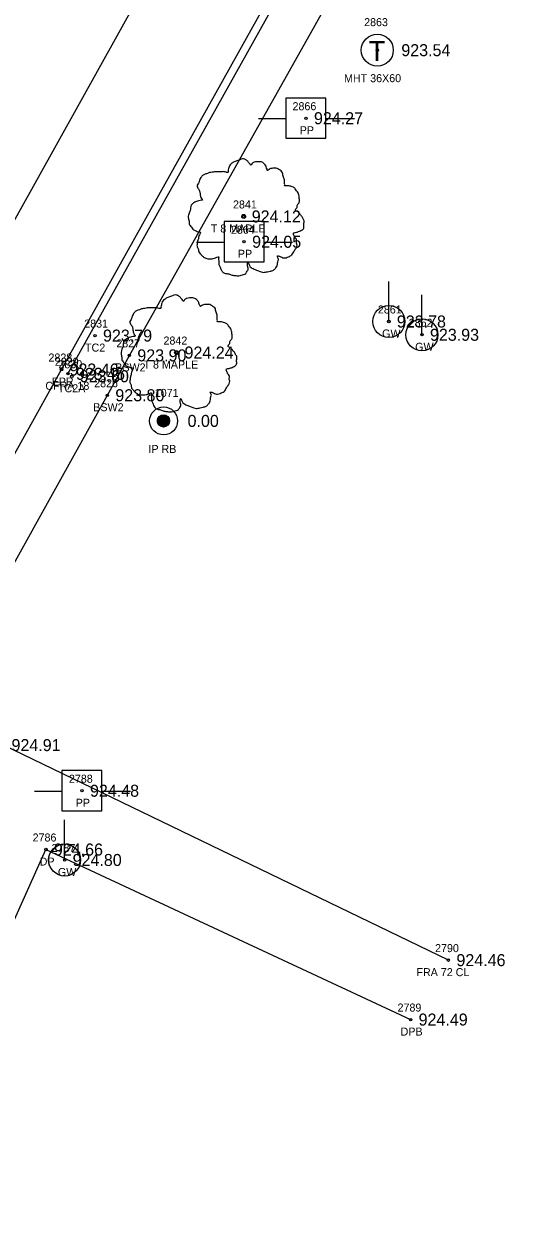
# Model space of a CAD drawing. Extents: x 1575382 to 1578175, y 1099175 to 1101955.
# Drawn here: x 1577042 to 1577102.8, y 1100555.1 to 1100704 of the extents above; entities that cross this region are included whole.
import ezdxf

# ---------------------------------------------------------------- set-up
doc = ezdxf.new("R2010")
doc.units = 0
for name, color, linetype in [('RD_EX_Conc', 7, 'Continuous'), ('RD_EX_Conc_txCode', 7, 'Continuous'), ('RD_EX_Driveway', 7, 'Continuous'), ('RD_EX_Driveway_txCode', 7, 'Continuous'), ('RD_EX_DV_Prop_txCode', 7, 'Continuous'), ('RD_EX_DV_PropPin', 7, 'Continuous'), ('RD_EX_Fence_Other', 7, 'Continuous'), ('RD_EX_Fence_Other_txCode', 7, 'Continuous'), ('RD_EX_Road', 7, 'Continuous'), ('RD_EX_Road_txCode', 7, 'Continuous'), ('RD_EX_SU_Telecom', 7, 'Continuous'), ('RD_EX_TX_Conc_ELEV', 7, 'Continuous'), ('RD_EX_TX_Driveway_ELEV', 7, 'Continuous'), ('RD_EX_TX_DV_Prop_ELEV', 7, 'Continuous'), ('RD_EX_TX_Fence_Other_ELEV', 7, 'Continuous'), ('RD_EX_TX_Road_ELEV', 7, 'Continuous'), ('RD_EX_TX_UT_ELEV', 7, 'Continuous'), ('RD_EX_TX_VEG_ELEV', 7, 'Continuous'), ('RD_EX_UT', 7, 'Continuous'), ('RD_EX_UT_txCode', 7, 'Continuous'), ('RD_EX_VEG', 7, 'Continuous'), ('RD_EX_VEG_txCode', 7, 'Continuous'), ('RD_HC_Cl', 7, 'Continuous'), ('RD_HC_Survey_ELEV', 7, 'Continuous'), ('RD_SMD_Locator', 7, 'Continuous')]:
    doc.layers.add(name, color=color, linetype=linetype)

msp = doc.modelspace()

# ---------------------------------------------------------------- linework, layer by layer
at = {"layer": 'RD_EX_Conc'}
for points in [[(1577047.47, 1100660.34), (1577079.61, 1100717.86), (1577079.61, 1100717.86), (1577102.32, 1100758.52), (1577114.19, 1100779.63), (1577126.08, 1100804.34)], [(1576925.28, 1100434.6), (1576931.32, 1100441.65), (1576943.72, 1100456.06), (1576959.8, 1100485.15), (1576962.79, 1100490.55), (1576976.91, 1100516.3), (1576979.99, 1100521.81), (1576994.08, 1100547.41), (1577013.9, 1100582.65), (1577028.01, 1100607.52), (1577031.93, 1100618.57), (1577033.8, 1100624.22), (1577052.4, 1100657.66), (1577055.15, 1100662.64), (1577085.17, 1100716.01)]]:
    msp.add_lwpolyline(points, dxfattribs=at)
at = {"layer": 'RD_EX_Driveway'}
msp.add_lwpolyline([(1577065.95, 1100460.35), (1577042.55, 1100463.11), (1577001.85, 1100499.13), (1577008.49, 1100516.59), (1577022.64, 1100551.7), (1577044.72, 1100600.92), (1577090.31, 1100579.68)], dxfattribs=at)
at = {"layer": 'RD_EX_DV_PropPin'}
for p, q in [((1577058.69, 1100654.26), (1577058.69, 1100654.65)), ((1577058.73, 1100654.16), (1577058.73, 1100654.75)), ((1577058.76, 1100654.08), (1577058.76, 1100654.82)), ((1577058.8, 1100654.03), (1577058.8, 1100654.88)), ((1577058.83, 1100653.98), (1577058.83, 1100654.93)), ((1577058.87, 1100653.94), (1577058.87, 1100654.97)), ((1577058.9, 1100653.9), (1577058.9, 1100655)), ((1577058.94, 1100653.87), (1577058.94, 1100655.04)), ((1577058.97, 1100653.84), (1577058.97, 1100655.06)), ((1577059.01, 1100653.82), (1577059.01, 1100655.09)), ((1577059.04, 1100653.8), (1577059.04, 1100655.11)), ((1577059.08, 1100653.78), (1577059.08, 1100655.13)), ((1577059.11, 1100653.76), (1577059.11, 1100655.15)), ((1577059.15, 1100653.75), (1577059.15, 1100655.16)), ((1577059.18, 1100653.73), (1577059.18, 1100655.17)), ((1577059.22, 1100653.72), (1577059.22, 1100655.18)), ((1577059.25, 1100653.71), (1577059.25, 1100655.19)), ((1577059.29, 1100653.7), (1577059.29, 1100655.2)), ((1577059.32, 1100653.7), (1577059.32, 1100655.21)), ((1577059.36, 1100653.7), (1577059.36, 1100655.21)), ((1577059.39, 1100653.69), (1577059.39, 1100655.21)), ((1577059.43, 1100653.69), (1577059.43, 1100655.21)), ((1577059.46, 1100653.69), (1577059.46, 1100655.21)), ((1577059.5, 1100653.7), (1577059.5, 1100655.21)), ((1577059.53, 1100653.7), (1577059.53, 1100655.21)), ((1577059.57, 1100653.7), (1577059.57, 1100655.2)), ((1577059.6, 1100653.71), (1577059.6, 1100655.19)), ((1577059.64, 1100653.72), (1577059.64, 1100655.18)), ((1577059.67, 1100653.73), (1577059.67, 1100655.17)), ((1577059.71, 1100653.75), (1577059.71, 1100655.16)), ((1577059.74, 1100653.76), (1577059.74, 1100655.15)), ((1577059.78, 1100653.78), (1577059.78, 1100655.13)), ((1577059.81, 1100653.8), (1577059.81, 1100655.11)), ((1577059.85, 1100653.82), (1577059.85, 1100655.09)), ((1577059.88, 1100653.84), (1577059.88, 1100655.06)), ((1577059.92, 1100653.87), (1577059.92, 1100655.04)), ((1577059.95, 1100653.9), (1577059.95, 1100655)), ((1577059.99, 1100653.94), (1577059.99, 1100654.97)), ((1577060.02, 1100653.98), (1577060.02, 1100654.93)), ((1577060.06, 1100654.03), (1577060.06, 1100654.88)), ((1577060.09, 1100654.08), (1577060.09, 1100654.82)), ((1577060.13, 1100654.16), (1577060.13, 1100654.75)), ((1577060.16, 1100654.26), (1577060.16, 1100654.65))]:
    msp.add_line(p, q, dxfattribs=at)
for radius in [1.75, 0.761]:
    msp.add_circle((1577059.43, 1100654.45), radius, dxfattribs=at)
at = {"layer": 'RD_EX_Fence_Other'}
msp.add_lwpolyline([(1577095.04, 1100587.1), (1577039.42, 1100613.96), (1576993.42, 1100500.9)], dxfattribs=at)
at = {"layer": 'RD_EX_Road'}
msp.add_lwpolyline([(1576918.43, 1100436.45), (1576919.69, 1100438.1), (1576919.21, 1100438.45), (1576924.62, 1100446.41), (1576935.15, 1100461.4), (1576954.41, 1100495.42), (1576968.8, 1100521.52), (1576985.92, 1100552.3), (1577005.62, 1100587.42), (1577028.14, 1100627.58), (1577046.67, 1100660.87), (1577078.76, 1100718.33)], dxfattribs=at)
at = {"layer": 'RD_EX_SU_Telecom'}
msp.add_circle((1577086.15, 1100700.76), 2, dxfattribs=at)
at = {"layer": 'RD_EX_UT'}
for p, q in [((1577079.72, 1100694.77), (1577074.72, 1100694.77)), ((1577074.72, 1100694.77), (1577074.72, 1100689.77)), ((1577079.72, 1100689.77), (1577079.72, 1100694.77)), ((1577071.29, 1100692.21), (1577074.76, 1100692.21)), ((1577079.65, 1100692.21), (1577083.29, 1100692.21)), ((1577074.72, 1100689.77), (1577079.72, 1100689.77)), ((1577072, 1100679.34), (1577067, 1100679.34)), ((1577067, 1100679.34), (1577067, 1100674.34)), ((1577072, 1100674.34), (1577072, 1100679.34)), ((1577063.56, 1100676.78), (1577067.03, 1100676.78)), ((1577071.92, 1100676.78), (1577075.56, 1100676.78)), ((1577067, 1100674.34), (1577072, 1100674.34)), ((1577087.59, 1100666.87), (1577087.59, 1100671.87)), ((1577091.73, 1100665.21), (1577091.73, 1100670.21)), ((1577051.72, 1100610.77), (1577046.72, 1100610.77)), ((1577046.72, 1100610.77), (1577046.72, 1100605.77)), ((1577051.72, 1100605.77), (1577051.72, 1100610.77)), ((1577043.29, 1100608.21), (1577046.76, 1100608.21)), ((1577051.65, 1100608.21), (1577055.29, 1100608.21)), ((1577046.72, 1100605.77), (1577051.72, 1100605.77)), ((1577047.06, 1100599.61), (1577047.06, 1100604.61))]:
    msp.add_line(p, q, dxfattribs=at)
for centre in [(1577087.59, 1100666.87), (1577091.73, 1100665.21), (1577047.06, 1100599.61)]:
    msp.add_circle(centre, 2, dxfattribs=at)
at = {"layer": 'RD_EX_VEG'}
for centre, radius in [((1577069.45, 1100679.99), 0.25), ((1577069.44, 1100679.97), 0.0001), ((1577061.05, 1100662.99), 0.25), ((1577061.03, 1100662.97), 0.0001)]:
    msp.add_circle(centre, radius, dxfattribs=at)
for points in [[(1577069.59, 1100687.16), (1577069.29, 1100687.18), (1577068.96, 1100687.08), (1577068.71, 1100686.98), (1577068.49, 1100686.91), (1577068.26, 1100686.81), (1577067.96, 1100686.63), (1577067.74, 1100686.43), (1577067.61, 1100686.18), (1577067.56, 1100685.96), (1577067.51, 1100685.68), (1577067.51, 1100685.51), (1577067.39, 1100685.48), (1577067.24, 1100685.51), (1577066.99, 1100685.58), (1577066.74, 1100685.58), (1577066.49, 1100685.58), (1577066.14, 1100685.56), (1577065.79, 1100685.56), (1577065.51, 1100685.51), (1577065.19, 1100685.46), (1577064.81, 1100685.33), (1577064.46, 1100685.21), (1577064.16, 1100684.96), (1577063.91, 1100684.48), (1577063.79, 1100684.13), (1577063.64, 1100683.88), (1577063.79, 1100683.43), (1577063.96, 1100683.08), (1577063.99, 1100682.88), (1577064.06, 1100682.46), (1577064.16, 1100682.23), (1577064.29, 1100682.03), (1577064.21, 1100682.01), (1577063.84, 1100681.96), (1577063.54, 1100681.86), (1577063.11, 1100681.63), (1577062.89, 1100681.41), (1577062.79, 1100681.08), (1577062.76, 1100680.73), (1577062.66, 1100680.53), (1577062.59, 1100680.26), (1577062.56, 1100680.18), (1577062.51, 1100679.86), (1577062.61, 1100679.41), (1577062.64, 1100679.06), (1577062.76, 1100678.84), (1577062.91, 1100678.66), (1577063.09, 1100678.41), (1577063.49, 1100678.19), (1577063.81, 1100678.09), (1577064.01, 1100678.06), (1577063.84, 1100677.56), (1577063.79, 1100677.21), (1577063.66, 1100676.81), (1577063.66, 1100676.74), (1577063.61, 1100676.26), (1577063.76, 1100675.94), (1577063.84, 1100675.56), (1577064.01, 1100675.34), (1577064.29, 1100675.04), (1577064.61, 1100674.81), (1577065.11, 1100674.69), (1577065.51, 1100674.71), (1577066.09, 1100674.89), (1577066.34, 1100674.96), (1577066.31, 1100674.79), (1577066.34, 1100674.41), (1577066.34, 1100673.99), (1577066.49, 1100673.66), (1577066.59, 1100673.39), (1577066.74, 1100673.14), (1577067.06, 1100672.91), (1577067.46, 1100672.84), (1577067.89, 1100672.69), (1577068.34, 1100672.61), (1577068.84, 1100672.59), (1577069.44, 1100672.74), (1577069.71, 1100672.86), (1577069.81, 1100673.04), (1577070.01, 1100673.41), (1577069.96, 1100673.64), (1577069.99, 1100674.24), (1577070.09, 1100674.06), (1577070.26, 1100673.71), (1577070.76, 1100673.41), (1577071.16, 1100673.24), (1577071.64, 1100673.09), (1577071.94, 1100673.01), (1577072.41, 1100673.09), (1577072.79, 1100673.16), (1577073.16, 1100673.29), (1577073.46, 1100673.56), (1577073.63, 1100673.84), (1577073.68, 1100674.11), (1577073.76, 1100674.49), (1577073.81, 1100674.66)], [(1577073.81, 1100674.66), (1577073.73, 1100674.84), (1577073.68, 1100675.09), (1577073.76, 1100675.06), (1577073.93, 1100675.01), (1577074.21, 1100674.89), (1577074.43, 1100674.81), (1577074.76, 1100674.84), (1577075.03, 1100674.94), (1577075.48, 1100675.21), (1577075.76, 1100675.69), (1577076.03, 1100676.09), (1577076.11, 1100676.41), (1577076.06, 1100676.64), (1577076.03, 1100677.14), (1577075.83, 1100677.39), (1577075.78, 1100677.51), (1577075.68, 1100677.91), (1577075.76, 1100677.96), (1577076.03, 1100678.01), (1577076.41, 1100678.14), (1577076.68, 1100678.26), (1577076.91, 1100678.44), (1577076.98, 1100678.66), (1577076.96, 1100679.06), (1577077.01, 1100679.46), (1577076.93, 1100679.61), (1577076.83, 1100679.76), (1577076.76, 1100679.96), (1577076.61, 1100680.11), (1577076.51, 1100680.26), (1577076.41, 1100680.36), (1577076.28, 1100680.51), (1577076.11, 1100680.63), (1577075.96, 1100680.68), (1577075.91, 1100680.83), (1577076.06, 1100681.03), (1577076.11, 1100681.13), (1577076.13, 1100681.36), (1577076.36, 1100681.71), (1577076.41, 1100682.11), (1577076.36, 1100682.53), (1577076.31, 1100682.81), (1577076.16, 1100683.08), (1577075.96, 1100683.33), (1577075.83, 1100683.51), (1577075.66, 1100683.63), (1577075.33, 1100683.76), (1577075.08, 1100683.81), (1577074.73, 1100683.81), (1577074.53, 1100683.86), (1577074.56, 1100683.91), (1577074.56, 1100684.06), (1577074.56, 1100684.33), (1577074.48, 1100684.78), (1577074.33, 1100685.28), (1577074.33, 1100685.31), (1577074.23, 1100685.56), (1577074.01, 1100685.76), (1577073.83, 1100685.86), (1577073.63, 1100685.98), (1577073.38, 1100686.01), (1577073.09, 1100686.01), (1577072.81, 1100685.96), (1577072.61, 1100685.86), (1577072.44, 1100685.73), (1577072.36, 1100685.88), (1577072.26, 1100686.18), (1577072.21, 1100686.33), (1577072.06, 1100686.51), (1577071.84, 1100686.71), (1577071.39, 1100686.83), (1577070.76, 1100686.76), (1577070.46, 1100686.56), (1577070.31, 1100686.38), (1577070.26, 1100686.51), (1577070.06, 1100686.71), (1577069.96, 1100686.88), (1577069.79, 1100687.01), (1577069.64, 1100687.11), (1577069.54, 1100687.16)], [(1577061.18, 1100670.16), (1577060.88, 1100670.18), (1577060.55, 1100670.08), (1577060.3, 1100669.98), (1577060.08, 1100669.91), (1577059.85, 1100669.81), (1577059.55, 1100669.63), (1577059.33, 1100669.43), (1577059.2, 1100669.18), (1577059.15, 1100668.96), (1577059.1, 1100668.68), (1577059.1, 1100668.51), (1577058.98, 1100668.48), (1577058.83, 1100668.51), (1577058.58, 1100668.58), (1577058.33, 1100668.58), (1577058.08, 1100668.58), (1577057.73, 1100668.56), (1577057.38, 1100668.56), (1577057.1, 1100668.51), (1577056.78, 1100668.46), (1577056.4, 1100668.33), (1577056.06, 1100668.21), (1577055.76, 1100667.96), (1577055.51, 1100667.49), (1577055.38, 1100667.14), (1577055.23, 1100666.89), (1577055.38, 1100666.44), (1577055.56, 1100666.09), (1577055.58, 1100665.89), (1577055.66, 1100665.46), (1577055.76, 1100665.24), (1577055.88, 1100665.04), (1577055.81, 1100665.01), (1577055.43, 1100664.96), (1577055.13, 1100664.86), (1577054.71, 1100664.64), (1577054.48, 1100664.41), (1577054.38, 1100664.09), (1577054.36, 1100663.74), (1577054.26, 1100663.54), (1577054.18, 1100663.26), (1577054.16, 1100663.19), (1577054.11, 1100662.86), (1577054.21, 1100662.41), (1577054.23, 1100662.06), (1577054.36, 1100661.84), (1577054.51, 1100661.66), (1577054.68, 1100661.41), (1577055.08, 1100661.19), (1577055.41, 1100661.09), (1577055.61, 1100661.06), (1577055.43, 1100660.56), (1577055.38, 1100660.21), (1577055.26, 1100659.81), (1577055.26, 1100659.74), (1577055.21, 1100659.26), (1577055.36, 1100658.94), (1577055.43, 1100658.56), (1577055.61, 1100658.34), (1577055.88, 1100658.04), (1577056.2, 1100657.81), (1577056.7, 1100657.69), (1577057.1, 1100657.71), (1577057.68, 1100657.89), (1577057.93, 1100657.96), (1577057.9, 1100657.79), (1577057.93, 1100657.41), (1577057.93, 1100656.99), (1577058.08, 1100656.67), (1577058.18, 1100656.39), (1577058.33, 1100656.14), (1577058.65, 1100655.92), (1577059.05, 1100655.84), (1577059.48, 1100655.69), (1577059.93, 1100655.62), (1577060.43, 1100655.59), (1577061.03, 1100655.74), (1577061.3, 1100655.87), (1577061.4, 1100656.04), (1577061.6, 1100656.42), (1577061.55, 1100656.64), (1577061.58, 1100657.24), (1577061.68, 1100657.06), (1577061.85, 1100656.71), (1577062.35, 1100656.42), (1577062.75, 1100656.24), (1577063.23, 1100656.09), (1577063.53, 1100656.02), (1577064, 1100656.09), (1577064.38, 1100656.17), (1577064.75, 1100656.29), (1577065.05, 1100656.57), (1577065.23, 1100656.84), (1577065.28, 1100657.11), (1577065.35, 1100657.49), (1577065.4, 1100657.66)], [(1577065.4, 1100657.66), (1577065.33, 1100657.84), (1577065.28, 1100658.09), (1577065.35, 1100658.06), (1577065.53, 1100658.01), (1577065.8, 1100657.89), (1577066.03, 1100657.81), (1577066.35, 1100657.84), (1577066.63, 1100657.94), (1577067.08, 1100658.21), (1577067.35, 1100658.69), (1577067.62, 1100659.09), (1577067.7, 1100659.41), (1577067.65, 1100659.64), (1577067.62, 1100660.14), (1577067.43, 1100660.39), (1577067.38, 1100660.51), (1577067.28, 1100660.91), (1577067.35, 1100660.96), (1577067.62, 1100661.01), (1577068, 1100661.14), (1577068.27, 1100661.26), (1577068.5, 1100661.44), (1577068.57, 1100661.66), (1577068.55, 1100662.06), (1577068.6, 1100662.46), (1577068.52, 1100662.61), (1577068.42, 1100662.76), (1577068.35, 1100662.96), (1577068.2, 1100663.11), (1577068.1, 1100663.26), (1577068, 1100663.36), (1577067.87, 1100663.51), (1577067.7, 1100663.64), (1577067.55, 1100663.69), (1577067.5, 1100663.84), (1577067.65, 1100664.04), (1577067.7, 1100664.14), (1577067.72, 1100664.36), (1577067.95, 1100664.71), (1577068, 1100665.11), (1577067.95, 1100665.54), (1577067.9, 1100665.81), (1577067.75, 1100666.09), (1577067.55, 1100666.34), (1577067.43, 1100666.51), (1577067.25, 1100666.64), (1577066.93, 1100666.76), (1577066.68, 1100666.81), (1577066.33, 1100666.81), (1577066.13, 1100666.86), (1577066.15, 1100666.91), (1577066.15, 1100667.06), (1577066.15, 1100667.34), (1577066.08, 1100667.79), (1577065.93, 1100668.28), (1577065.93, 1100668.31), (1577065.83, 1100668.56), (1577065.6, 1100668.76), (1577065.43, 1100668.86), (1577065.23, 1100668.98), (1577064.98, 1100669.01), (1577064.68, 1100669.01), (1577064.4, 1100668.96), (1577064.2, 1100668.86), (1577064.03, 1100668.73), (1577063.95, 1100668.88), (1577063.85, 1100669.18), (1577063.8, 1100669.33), (1577063.65, 1100669.51), (1577063.43, 1100669.71), (1577062.98, 1100669.83), (1577062.35, 1100669.76), (1577062.05, 1100669.56), (1577061.9, 1100669.38), (1577061.85, 1100669.51), (1577061.65, 1100669.71), (1577061.55, 1100669.88), (1577061.38, 1100670.01), (1577061.23, 1100670.11), (1577061.13, 1100670.16)]]:
    msp.add_spline(points, degree=3, dxfattribs=at)
at = {"layer": 'RD_HC_Cl'}
msp.add_line((1576888.29, 1100406.32), (1577092.18, 1100771.63), dxfattribs=at)
at = {"layer": 'RD_SMD_Locator'}
for centre in [(1577086.15, 1100700.76), (1577077.23, 1100692.26), (1577069.45, 1100679.99), (1577069.5, 1100676.83), (1577087.59, 1100666.87), (1577050.86, 1100665.11), (1577091.73, 1100665.21), (1577055.15, 1100662.64), (1577061.05, 1100662.99), (1577046.67, 1100660.87), (1577047.47, 1100660.34), (1577047.96, 1100660.03), (1577052.4, 1100657.66), (1577059.43, 1100654.45), (1577049.23, 1100608.26), (1577044.72, 1100600.92), (1577047.06, 1100599.61), (1577095.04, 1100587.1), (1577090.31, 1100579.68)]:
    msp.add_circle(centre, 0.15, dxfattribs=at)

# ---------------------------------------------------------------- texts
at = {"layer": 'RD_EX_Conc_txCode'}
for s, p in [('2831', (1577049.51, 1100666.11)), ('2827', (1577053.52, 1100663.64)), ('TC2', (1577049.61, 1100663.11)), ('2829', (1577045.84, 1100661.34)), ('2830', (1577046.29, 1100661.03)), ('BSW2', (1577053.39, 1100660.64)), ('CFRA 18', (1577044.65, 1100658.34)), ('TC2A', (1577046.23, 1100658.03)), ('2826', (1577050.75, 1100658.66)), ('BSW2', (1577050.64, 1100655.66))]:
    msp.add_text(s, height=1, dxfattribs=at).set_placement(p)
at = {"layer": 'RD_EX_Driveway_txCode'}
for s, p in [('2786', (1577043.06, 1100601.92)), ('DP', (1577043.94, 1100598.92)), ('2789', (1577088.68, 1100580.68)), ('DPB', (1577089.06, 1100577.68))]:
    msp.add_text(s, height=1, dxfattribs=at).set_placement(p)
at = {"layer": 'RD_EX_DV_Prop_txCode'}
for s, p in [('1071', (1577058.33, 1100657.45)), ('IP RB', (1577057.54, 1100650.45))]:
    msp.add_text(s, height=1, dxfattribs=at).set_placement(p)
at = {"layer": 'RD_EX_Fence_Other_txCode'}
for s, p in [('2790', (1577093.37, 1100588.1)), ('FRA 72 CL', (1577091.04, 1100585.1))]:
    msp.add_text(s, height=1, dxfattribs=at).set_placement(p)
at = {"layer": 'RD_EX_Road_txCode'}
for s, p in [('2828', (1577045.04, 1100661.87)), ('EPR', (1577045.44, 1100658.87))]:
    msp.add_text(s, height=1, dxfattribs=at).set_placement(p)
at = {"layer": 'RD_EX_SU_Telecom'}
msp.add_text('T', height=2.5, dxfattribs=at).set_placement((1577085.09, 1100699.39))
at = {"layer": 'RD_EX_TX_Conc_ELEV'}
for s, p in [('923.79', (1577051.86, 1100664.36)), ('923.90', (1577056.15, 1100661.89)), ('923.45', (1577048.47, 1100659.59)), ('923.60', (1577048.96, 1100659.28)), ('923.80', (1577053.4, 1100656.91))]:
    msp.add_text(s, height=1.5, dxfattribs=at).set_placement(p)
at = {"layer": 'RD_EX_TX_Driveway_ELEV'}
for s, p in [('924.66', (1577045.72, 1100600.17)), ('924.49', (1577091.31, 1100578.93))]:
    msp.add_text(s, height=1.5, dxfattribs=at).set_placement(p)
at = {"layer": 'RD_EX_TX_DV_Prop_ELEV'}
msp.add_text('0.00', height=1.5, dxfattribs=at).set_placement((1577062.43, 1100653.7))
at = {"layer": 'RD_EX_TX_Fence_Other_ELEV'}
for s, p in [('924.91', (1577040.42, 1100613.21)), ('924.46', (1577096.04, 1100586.35))]:
    msp.add_text(s, height=1.5, dxfattribs=at).set_placement(p)
at = {"layer": 'RD_EX_TX_Road_ELEV'}
msp.add_text('923.46', height=1.5, dxfattribs=at).set_placement((1577047.67, 1100660.12))
at = {"layer": 'RD_EX_TX_UT_ELEV'}
for s, p in [('923.54', (1577089.15, 1100700.01)), ('923.78', (1577088.59, 1100666.12)), ('923.93', (1577092.73, 1100664.46)), ('924.80', (1577048.06, 1100598.86))]:
    msp.add_text(s, height=1.5, dxfattribs=at).set_placement(p)
at = {"layer": 'RD_EX_TX_VEG_ELEV'}
for s, p in [('924.12', (1577070.45, 1100679.24)), ('924.24', (1577062.05, 1100662.24))]:
    msp.add_text(s, height=1.5, dxfattribs=at).set_placement(p)
at = {"layer": 'RD_EX_UT_txCode'}
for s, p in [('2863', (1577084.5, 1100703.76)), ('MHT 36X60', (1577081.99, 1100696.76)), ('2866', (1577075.55, 1100693.26)), ('PP', (1577076.45, 1100690.26)), ('2864', (1577067.85, 1100677.83)), ('PP', (1577068.72, 1100674.83)), ('2861', (1577086.22, 1100667.87)), ('2862', (1577090.07, 1100666.21)), ('GW', (1577086.75, 1100664.87)), ('GW', (1577090.88, 1100663.21)), ('2788', (1577047.6, 1100609.26)), ('PP', (1577048.45, 1100606.26)), ('2787', (1577045.43, 1100600.61)), ('GW', (1577046.22, 1100597.61))]:
    msp.add_text(s, height=1, dxfattribs=at).set_placement(p)
at = {"layer": 'RD_EX_VEG_txCode'}
for s, p in [('2841', (1577068.11, 1100680.99)), ('T 8 MAPLE', (1577065.33, 1100677.99)), ('2842', (1577059.42, 1100663.99)), ('T 8 MAPLE', (1577056.92, 1100660.99))]:
    msp.add_text(s, height=1, dxfattribs=at).set_placement(p)
at = {"layer": 'RD_HC_Survey_ELEV'}
for s, p in [('924.27', (1577078.23, 1100691.51)), ('924.05', (1577070.5, 1100676.08)), ('924.48', (1577050.23, 1100607.51))]:
    msp.add_text(s, height=1.5, dxfattribs=at).set_placement(p)

doc.saveas('drawing.dxf')
